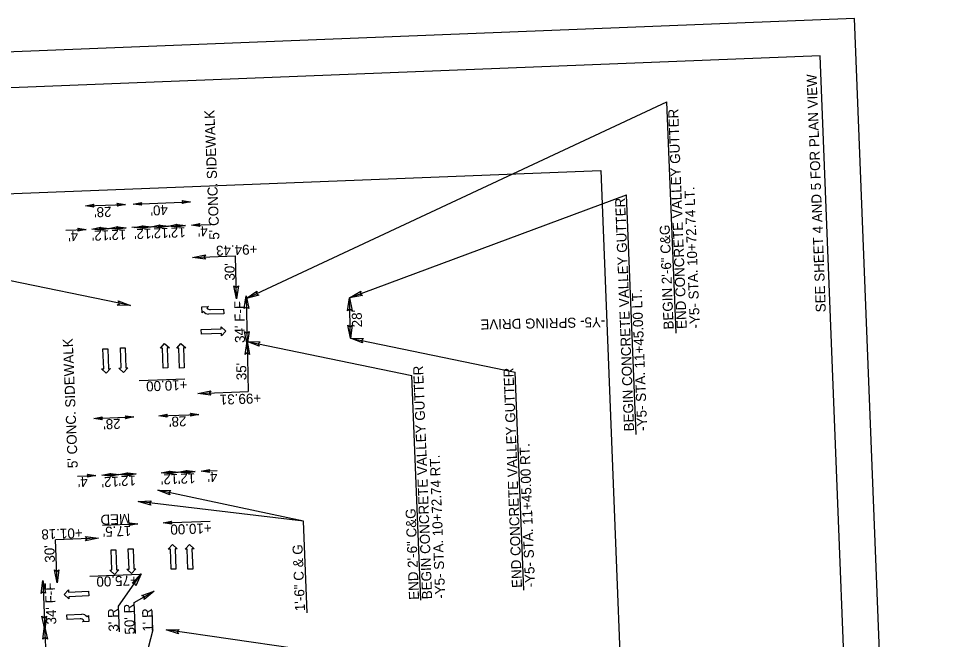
# Model space of a CAD drawing. Extents: x 1627847 to 1629013, y 761524 to 763498.
# Drawn here: x 1628362 to 1629013, y 762832 to 763266 of the extents above; entities that cross this region are included whole.
import ezdxf

# ---------------------------------------------------------------- set-up
doc = ezdxf.new("R2010")
doc.units = 0
for name, color, linetype in [('Default', 7, 'Continuous'), ('Prop Dimension', 7, 'Continuous'), ('Prop Dimension Text', 7, 'Continuous'), ('Prop DSN Text', 7, 'Continuous'), ('Prop Horizontal Alignment Tick Small', 7, 'Continuous'), ('Prop Lane Arrow CELL', 7, 'Continuous'), ('Prop Terminator CELL', 7, 'Continuous'), ('Sheet Clip Boundary CELL', 7, 'Continuous'), ('Sheet Plan And Profile CELL', 7, 'Continuous'), ('Sheet Plot Border Outside CELL', 7, 'Continuous')]:
    doc.layers.add(name, color=color, linetype=linetype)

msp = doc.modelspace()

# ---------------------------------------------------------------- linework, layer by layer
at = {"layer": 'Prop Dimension'}
for p, q in [((1628821.65, 763046.08), (1628815.27, 763207.88)), ((1628593.38, 763070.78), (1628787.01, 763142.85)), ((1628793.61, 762975.29), (1628787.01, 763142.85)), ((1628408.71, 763135.02), (1628436.69, 763136.13)), ((1628442.19, 763136.34), (1628482.16, 763137.92)), ((1628425.35, 763119.31), (1628437.34, 763119.79)), ((1628442.83, 763120), (1628454.82, 763120.48)), ((1628454.82, 763120.48), (1628466.81, 763120.95)), ((1628466.81, 763120.95), (1628478.8, 763121.42)), ((1628482.8, 763121.58), (1628496.53, 763122.12)), ((1628440.23, 763065.41), (1628206.11, 763113.58)), ((1628395.05, 763118.12), (1628409.36, 763118.68)), ((1628413.35, 763118.84), (1628425.35, 763119.31)), ((1628483.69, 763098.99), (1628513.67, 763100.17)), ((1628514.27, 763070.18), (1628513.67, 763100.17)), ((1628521.08, 763072.32), (1628521.76, 763038.32)), ((1628593.94, 763042.65), (1628593.38, 763070.78)), ((1628593.94, 763042.65), (1628709.19, 763018.94)), ((1628521.72, 763040.32), (1628522.41, 763005.33)), ((1628521.72, 763040.32), (1628636.96, 763016.61)), ((1628643.15, 762859.67), (1628636.96, 763016.61)), ((1628715.2, 762866.6), (1628709.19, 763018.94)), ((1628446.3, 763013.02), (1628478.18, 763014.28)), ((1628487.44, 763003.95), (1628522.41, 763005.33)), ((1628414.53, 762986.54), (1628442.51, 762987.64)), ((1628460, 762988.33), (1628487.97, 762989.44)), ((1628403.15, 762946.27), (1628416.14, 762946.78)), ((1628420.13, 762946.94), (1628432.12, 762947.41)), ((1628432.12, 762947.41), (1628444.11, 762947.89)), ((1628461.6, 762948.58), (1628473.59, 762949.05)), ((1628473.59, 762949.05), (1628485.58, 762949.52)), ((1628489.58, 762949.68), (1628500.89, 762950.12)), ((1628561.3, 762914.8), (1628459.31, 762936.54)), ((1628561.3, 762914.8), (1628445.63, 762928.53)), ((1628420.79, 762911.94), (1628445.49, 762912.91)), ((1628462.98, 762913.6), (1628495.88, 762914.9)), ((1628563.83, 762850.73), (1628561.3, 762914.8)), ((1628417.86, 762902.99), (1628387.89, 762901.81)), ((1628389.08, 762871.83), (1628387.89, 762901.81)), ((1628378.98, 762873.43), (1628380.33, 762839.46)), ((1628446.88, 762877.64), (1628411.91, 762876.26)), ((1628431.88, 762855.46), (1628447.82, 762878.08)), ((1628442.79, 762857.98), (1628456.86, 762865.93)), ((1628432.58, 762837.58), (1628431.88, 762855.46)), ((1628443.65, 762836.33), (1628442.79, 762857.98)), ((1628455.98, 762838.88), (1628455.44, 762852.53)), ((1628380.25, 762841.46), (1628381.83, 762801.49)), ((1628455.98, 762838.88), (1628450.91, 762820.05)), ((1628555.02, 762825.91), (1628465.18, 762838.91))]:
    msp.add_line(p, q, dxfattribs=at)
at = {"layer": 'Prop Dimension Text'}
msp.add_line((1628521.12, 763070.32), (1628815.27, 763207.88), dxfattribs=at)
at = {"layer": 'Prop Horizontal Alignment Tick Small'}
msp.add_line((1628446.08, 763120.13), (1628441.08, 763119.93), dxfattribs=at)
at = {"layer": 'Prop Lane Arrow CELL'}
for p, q in [((1628490.2, 763064.68), (1628494.7, 763064.85)), ((1628490.37, 763060.28), (1628490.2, 763064.68)), ((1628491.39, 763061.36), (1628490.37, 763060.28)), ((1628494.7, 763064.85), (1628493.67, 763063.77)), ((1628496.2, 763062.69), (1628505.35, 763062.94)), ((1628505.35, 763062.94), (1628505.44, 763059.64)), ((1628505.44, 763059.64), (1628494.9, 763059.35)), ((1628489.75, 763048.85), (1628503.74, 763049.18)), ((1628489.82, 763045.55), (1628489.75, 763048.85)), ((1628503.74, 763049.18), (1628503.71, 763050.68)), ((1628503.71, 763050.68), (1628506.93, 763047.65)), ((1628503.82, 763045.88), (1628489.82, 763045.55)), ((1628503.85, 763044.38), (1628503.82, 763045.88)), ((1628506.93, 763047.65), (1628503.85, 763044.38)), ((1628421.01, 763035.21), (1628424.31, 763035.33)), ((1628421.51, 763021.22), (1628421.01, 763035.21)), ((1628424.31, 763035.33), (1628424.81, 763021.34)), ((1628433.16, 763035.88), (1628436.45, 763035.99)), ((1628433.66, 763021.89), (1628433.16, 763035.88)), ((1628436.45, 763035.99), (1628436.96, 763022)), ((1628461.12, 763035.71), (1628464.1, 763038.97)), ((1628462.61, 763035.76), (1628461.12, 763035.71)), ((1628463.12, 763021.77), (1628462.61, 763035.76)), ((1628464.1, 763038.97), (1628467.41, 763035.94)), ((1628467.41, 763035.94), (1628465.91, 763035.88)), ((1628465.91, 763035.88), (1628466.42, 763021.89)), ((1628472.55, 763035.69), (1628475.54, 763038.95)), ((1628474.05, 763035.74), (1628472.55, 763035.69)), ((1628474.55, 763021.75), (1628474.05, 763035.74)), ((1628475.54, 763038.95), (1628478.85, 763035.91)), ((1628478.85, 763035.91), (1628477.35, 763035.86)), ((1628477.35, 763035.86), (1628477.85, 763021.87)), ((1628438.46, 763022.06), (1628435.47, 763018.8)), ((1628436.96, 763022), (1628438.46, 763022.06)), ((1628420.01, 763021.16), (1628421.51, 763021.22)), ((1628423.32, 763018.13), (1628420.01, 763021.16)), ((1628426.31, 763021.39), (1628423.32, 763018.13)), ((1628424.81, 763021.34), (1628426.31, 763021.39)), ((1628432.16, 763021.83), (1628433.66, 763021.89)), ((1628435.47, 763018.8), (1628432.16, 763021.83)), ((1628466.42, 763021.89), (1628463.12, 763021.77)), ((1628477.85, 763021.87), (1628474.55, 763021.75)), ((1628466.64, 762895.23), (1628469.63, 762898.49)), ((1628469.63, 762898.49), (1628472.94, 762895.46)), ((1628478.45, 762895.22), (1628481.43, 762898.48)), ((1628481.43, 762898.48), (1628484.74, 762895.45)), ((1628426.75, 762894.74), (1628430.05, 762894.86)), ((1628427.26, 762880.75), (1628426.75, 762894.74)), ((1628430.05, 762894.86), (1628430.56, 762880.87)), ((1628438.73, 762895.4), (1628442.03, 762895.52)), ((1628439.23, 762881.41), (1628438.73, 762895.4)), ((1628442.03, 762895.52), (1628442.53, 762881.53)), ((1628468.14, 762895.29), (1628466.64, 762895.23)), ((1628468.65, 762881.3), (1628468.14, 762895.29)), ((1628472.94, 762895.46), (1628471.44, 762895.41)), ((1628471.44, 762895.41), (1628471.94, 762881.41)), ((1628479.95, 762895.28), (1628478.45, 762895.22)), ((1628480.45, 762881.29), (1628479.95, 762895.28)), ((1628484.74, 762895.45), (1628483.24, 762895.4)), ((1628483.24, 762895.4), (1628483.75, 762881.41)), ((1628425.76, 762880.7), (1628427.26, 762880.75)), ((1628429.07, 762877.66), (1628425.76, 762880.7)), ((1628432.05, 762880.92), (1628429.07, 762877.66)), ((1628430.56, 762880.87), (1628432.05, 762880.92)), ((1628437.73, 762881.36), (1628439.23, 762881.41)), ((1628441.05, 762878.32), (1628437.73, 762881.36)), ((1628444.03, 762881.58), (1628441.05, 762878.32)), ((1628442.53, 762881.53), (1628444.03, 762881.58)), ((1628471.94, 762881.41), (1628468.65, 762881.3)), ((1628483.75, 762881.41), (1628480.45, 762881.29)), ((1628393.88, 762863.53), (1628396.91, 762866.85)), ((1628396.91, 762866.85), (1628396.96, 762865.35)), ((1628396.96, 762865.35), (1628410.95, 762865.9)), ((1628410.95, 762865.9), (1628411.08, 762862.6)), ((1628397.15, 762860.55), (1628393.88, 762863.53)), ((1628411.08, 762862.6), (1628397.09, 762862.05)), ((1628397.09, 762862.05), (1628397.15, 762860.55)), ((1628395.8, 762849.5), (1628406.34, 762849.92)), ((1628395.93, 762846.2), (1628395.8, 762849.5)), ((1628405.07, 762846.56), (1628395.93, 762846.2)), ((1628409.87, 762847.95), (1628410.88, 762849.04)), ((1628410.88, 762849.04), (1628411.1, 762844.65)), ((1628406.6, 762844.42), (1628407.61, 762845.51)), ((1628411.1, 762844.65), (1628406.6, 762844.42))]:
    msp.add_line(p, q, dxfattribs=at)
for centre, radius, start, end in [((1628495.55, 763064.55), 5.25, 217.57411, 262.88581), ((1628496.11, 763065.95), 3.28, 221.90371, 271.56188), ((1628405.21, 762843.31), 3.28, 42.60001, 92.25819), ((1628405.75, 762844.71), 5.25, 38.27042, 83.58212)]:
    msp.add_arc(centre, radius, start, end, dxfattribs=at)
at = {"layer": 'Prop Terminator CELL'}
for points in [[(1628414.59, 763134.19), (1628408.71, 763135.02), (1628414.56, 763136.24), (1628413.85, 763135.18)], [(1628430.81, 763136.96), (1628436.69, 763136.13), (1628430.84, 763134.91), (1628431.56, 763135.97)], [(1628448.07, 763135.51), (1628442.19, 763136.34), (1628448.04, 763137.56), (1628447.32, 763136.5)], [(1628476.28, 763138.75), (1628482.16, 763137.92), (1628476.31, 763136.7), (1628477.02, 763137.77)], [(1628419.24, 763118.06), (1628413.35, 763118.84), (1628419.19, 763120.11), (1628418.49, 763119.04)], [(1628419.46, 763120.09), (1628425.35, 763119.31), (1628419.51, 763118.04), (1628420.21, 763119.11)], [(1628431.23, 763118.54), (1628425.35, 763119.31), (1628431.18, 763120.58), (1628430.48, 763119.52)], [(1628431.45, 763120.56), (1628437.34, 763119.79), (1628431.5, 763118.52), (1628432.21, 763119.58)], [(1628448.72, 763119.23), (1628442.83, 763120), (1628448.67, 763121.27), (1628447.96, 763120.21)], [(1628448.94, 763121.25), (1628454.82, 763120.48), (1628448.99, 763119.2), (1628449.69, 763120.27)], [(1628460.71, 763119.7), (1628454.82, 763120.48), (1628460.66, 763121.75), (1628459.95, 763120.68)], [(1628460.93, 763121.72), (1628466.81, 763120.95), (1628460.98, 763119.68), (1628461.68, 763120.75)], [(1628472.7, 763120.17), (1628466.81, 763120.95), (1628472.65, 763122.22), (1628471.94, 763121.15)], [(1628472.92, 763122.2), (1628478.8, 763121.42), (1628472.97, 763120.15), (1628473.67, 763121.22)], [(1628488.69, 763120.8), (1628482.8, 763121.58), (1628488.64, 763122.85), (1628487.93, 763121.78)], [(1628403.47, 763119.46), (1628409.36, 763118.68), (1628403.52, 763117.41), (1628404.23, 763118.48)], [(1628492.75, 763097.8), (1628483.69, 763098.99), (1628492.67, 763100.95), (1628491.59, 763099.3)], [(1628515.64, 763079.21), (1628514.27, 763070.18), (1628512.49, 763079.2), (1628514.11, 763078.08)], [(1628529.93, 763072.72), (1628521.12, 763070.32), (1628528.64, 763075.6), (1628528.27, 763073.66)], [(1628602.36, 763072.47), (1628593.38, 763070.78), (1628601.31, 763075.44), (1628600.79, 763073.54)], [(1628431.73, 763068.74), (1628440.23, 763065.41), (1628431.04, 763065.66), (1628432.49, 763067)], [(1628519.71, 763063.29), (1628521.08, 763072.32), (1628522.86, 763063.3), (1628521.24, 763064.42)], [(1628592.01, 763061.75), (1628593.38, 763070.78), (1628595.16, 763061.77), (1628593.54, 763062.88)], [(1628595.31, 763051.68), (1628593.94, 763042.65), (1628592.16, 763051.67), (1628593.79, 763050.55)], [(1628523.13, 763047.35), (1628521.76, 763038.32), (1628519.98, 763047.34), (1628521.6, 763046.22)], [(1628602.45, 763039.32), (1628593.94, 763042.65), (1628603.13, 763042.39), (1628601.68, 763041.06)], [(1628520.34, 763031.29), (1628521.72, 763040.32), (1628523.5, 763031.31), (1628521.87, 763032.42)], [(1628530.22, 763036.99), (1628521.72, 763040.32), (1628530.9, 763040.07), (1628529.45, 763038.73)], [(1628496.49, 763002.76), (1628487.44, 763003.95), (1628496.42, 763005.91), (1628495.33, 763004.26)], [(1628465.87, 762987.5), (1628460, 762988.33), (1628465.84, 762989.55), (1628465.13, 762988.49)], [(1628482.1, 762990.27), (1628487.97, 762989.44), (1628482.13, 762988.22), (1628482.84, 762989.28)], [(1628420.41, 762985.71), (1628414.53, 762986.54), (1628420.38, 762987.76), (1628419.66, 762986.7)], [(1628436.63, 762988.47), (1628442.51, 762987.64), (1628436.66, 762986.43), (1628437.38, 762987.49)], [(1628495.46, 762948.9), (1628489.58, 762949.68), (1628495.42, 762950.95), (1628494.71, 762949.88)], [(1628410.25, 762947.56), (1628416.14, 762946.78), (1628410.3, 762945.51), (1628411.01, 762946.58)], [(1628426.02, 762946.16), (1628420.13, 762946.94), (1628425.97, 762948.21), (1628425.26, 762947.14)], [(1628426.24, 762948.19), (1628432.12, 762947.41), (1628426.29, 762946.14), (1628426.99, 762947.21)], [(1628438.01, 762946.64), (1628432.12, 762947.41), (1628437.96, 762948.68), (1628437.25, 762947.62)], [(1628438.23, 762948.66), (1628444.11, 762947.89), (1628438.28, 762946.61), (1628438.98, 762947.68)], [(1628467.49, 762947.8), (1628461.6, 762948.58), (1628467.44, 762949.85), (1628466.73, 762948.78)], [(1628467.71, 762949.82), (1628473.59, 762949.05), (1628467.75, 762947.78), (1628468.46, 762948.85)], [(1628479.48, 762948.27), (1628473.59, 762949.05), (1628479.43, 762950.32), (1628478.72, 762949.25)], [(1628479.7, 762950.3), (1628485.58, 762949.52), (1628479.75, 762948.25), (1628480.45, 762949.32)], [(1628467.79, 762933.14), (1628459.31, 762936.54), (1628468.49, 762936.21), (1628467.03, 762934.89)], [(1628454.38, 762925.93), (1628445.63, 762928.53), (1628454.8, 762929.06), (1628453.47, 762927.6)], [(1628439.62, 762913.74), (1628445.49, 762912.91), (1628439.65, 762911.7), (1628440.36, 762912.76)], [(1628468.86, 762912.77), (1628462.98, 762913.6), (1628468.83, 762914.82), (1628468.11, 762913.76)], [(1628408.81, 762904.19), (1628417.86, 762902.99), (1628408.88, 762901.04), (1628409.97, 762902.68)], [(1628390.27, 762880.89), (1628389.08, 762871.83), (1628387.12, 762880.81), (1628388.76, 762879.73)], [(1628377.79, 762864.38), (1628378.98, 762873.43), (1628380.94, 762864.45), (1628379.29, 762865.54)], [(1628441.37, 762871.61), (1628447.82, 762878.08), (1628443.92, 762869.76), (1628443.27, 762871.62)], [(1628448.26, 762862.85), (1628456.86, 762865.93), (1628449.76, 762860.08), (1628449.98, 762862.04)], [(1628381.52, 762848.52), (1628380.33, 762839.46), (1628378.37, 762848.44), (1628380.01, 762847.35)], [(1628379.06, 762832.41), (1628380.25, 762841.46), (1628382.21, 762832.48), (1628380.56, 762833.57)], [(1628473.86, 762836.08), (1628465.18, 762838.91), (1628474.36, 762839.2), (1628472.99, 762837.78)]]:
    msp.add_lwpolyline(points, close=True, dxfattribs=at)
at = {"layer": 'Sheet Clip Boundary CELL'}
msp.add_lwpolyline([(1628097.28, 762511.58), (1628072.8, 763132.43), (1628198.63, 763137.39), (1628215.93, 763082.79), (1628256.43, 763089.13), (1628269.19, 763140.18), (1628768.96, 763159.88), (1628793.44, 762539.03)], close=True, dxfattribs=at)
at = {"layer": 'Sheet Plan And Profile CELL'}
msp.add_lwpolyline([(1627873.18, 763198.56), (1627932.28, 761699.73), (1628981.47, 761741.1), (1628922.36, 763239.94)], close=True, dxfattribs=at)
at = {"layer": 'Sheet Plot Border Outside CELL'}
msp.add_lwpolyline([(1629013.34, 761567.22), (1628946.36, 763265.9), (1627847.21, 763222.56), (1627914.2, 761523.88)], close=True, dxfattribs=at)

# ---------------------------------------------------------------- texts
at = {"layer": 'Default'}
msp.add_text('SEE SHEET 4 AND 5 FOR PLAN VIEW', height=7, rotation=92.25819, dxfattribs=at).set_placement((1628926.33, 763060.89))
at = {"layer": 'Prop Dimension'}
for s, p in [('+94.43', (1628528.82, 763108.29)), ('+10.00', (1628479.93, 763013.57)), ('+10.00', (1628496.85, 762913.49)), ('+75.00', (1628445.18, 762877.1))]:
    msp.add_text(s, height=7, rotation=182.25819, dxfattribs=at).set_placement(p)
at = {"layer": 'Prop Dimension Text'}
for s, rotation, p in [('END CONCRETE VALLEY GUTTER', 92.25819, (1628829.12, 763049.23)), ('-Y5- STA. 10+72.74 LT.', 92.25819, (1628838.29, 763049.59)), ('BEGIN CONCRETE VALLEY GUTTER', 92.25819, (1628792.32, 762977.71)), ("28'", 182.25819, (1628426.82, 763134.52)), ("40'", 182.25819, (1628466.26, 763135.79)), ("12'", 182.25819, (1628466.69, 763119.78)), ("12'", 182.25819, (1628478.68, 763120.25)), ("4'", 182.25819, (1628494.12, 763120.93)), ('BEGIN 2\'-6" C&G', 92.25819, (1628819.95, 763048.87)), ("4'", 182.25819, (1628403.53, 763117.59)), ("12'", 182.25819, (1628425.22, 763118.14)), ("12'", 182.25819, (1628437.21, 763118.61)), ("12'", 182.25819, (1628454.75, 763119.31)), ("30'", 91.02555, (1628513.2, 763082.95)), ('-Y5- STA. 11+45.00 LT.', 92.25819, (1628801.49, 762978.07)), ("34' F-F", 91.14069, (1628520.31, 763039.41)), ("28'", 91.14069, (1628602.1, 763050.32)), ("35'", 91.02555, (1628521.36, 763013.36)), ('BEGIN CONCRETE VALLEY GUTTER', 92.25819, (1628651.16, 762860.39)), ('END CONCRETE VALLEY GUTTER', 92.25819, (1628713.93, 762868.34)), ('+99.31', 182.25819, (1628531.45, 763004.25)), ("28'", 182.25819, (1628433.25, 762986.41)), ("28'", 182.25819, (1628479.19, 762988.18)), ('-Y5- STA. 11+45.00 RT.', 92.25819, (1628723.1, 762868.7)), ('-Y5- STA. 10+72.74 RT.', 92.25819, (1628660.32, 762860.75)), ("4'", 182.25819, (1628410.25, 762945.83)), ("12'", 182.25819, (1628432.03, 762945.99)), ("12'", 182.25819, (1628443.89, 762946.74)), ("12'", 182.25819, (1628473.52, 762947.89)), ("12'", 182.25819, (1628485.46, 762948.35)), ("4'", 182.25819, (1628500.87, 762949.42)), ('MED', 182.25819, (1628439.93, 762920.08)), ('END 2\'-6" C&G', 92.25819, (1628641.99, 762860.03)), ("17.5'", 182.25819, (1628440.68, 762911.64)), ('+01.18', 182.25819, (1628406.68, 762910.1)), ("30'", 92.27234, (1628387.48, 762885.98)), ("34' F-F", 92.27234, (1628388.44, 762842.77)), ("3' R", 92.25819, (1628432.02, 762837.82)), ("50' R", 92.25819, (1628443.35, 762835.77)), ("1' R", 92.25819, (1628455.9, 762837.8))]:
    msp.add_text(s, height=7, rotation=rotation, dxfattribs=at).set_placement(p)
at = {"layer": 'Prop DSN Text'}
for s, rotation, p in [("5' CONC. SIDEWALK", 92.25819, (1628502.45, 763111.62)), ('-Y5- SPRING DRIVE', 181.14069, (1628772.1, 763057.43)), ("5' CONC. SIDEWALK", 92.25819, (1628403.45, 762952.02)), ('1\'-6" C & G', 92.25819, (1628562.28, 762852.11))]:
    msp.add_text(s, height=7, rotation=rotation, dxfattribs=at).set_placement(p)

doc.saveas('drawing.dxf')
